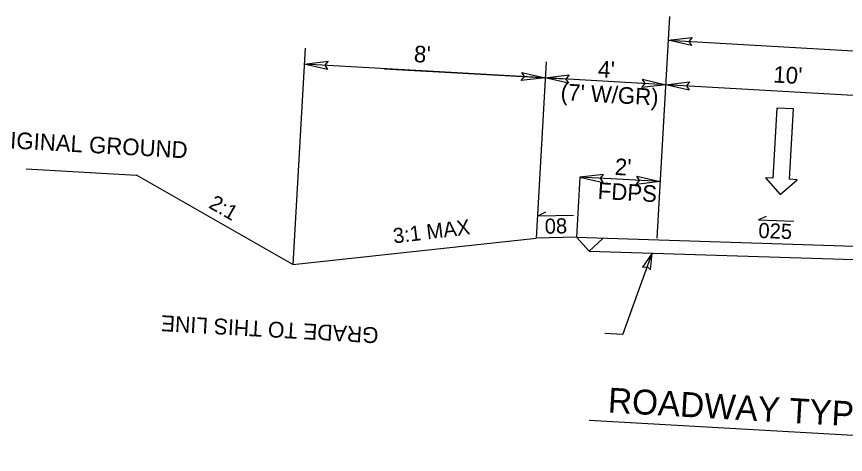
# Model space of a CAD drawing. Extents: x 2604316 to 2606605, y 617090 to 619543.
# Drawn here: x 2605915 to 2606244.6, y 617090 to 617264.2 of the extents above; entities that cross this region are included whole.
import ezdxf

# ---------------------------------------------------------------- set-up
doc = ezdxf.new("R2010")
doc.units = 0
for name, color, linetype in [('Pattern 1', 7, 'Continuous'), ('Prop Vertical Profile Curve Label', 7, 'Continuous'), ('Typical Pavement Slope CELL', 7, 'Continuous'), ('Typical Pavement Slope Information CELL', 7, 'Continuous'), ('Typical Terminator CELL', 7, 'Continuous'), ('Typical Text General CELL', 7, 'Continuous')]:
    doc.layers.add(name, color=color, linetype=linetype)

msp = doc.modelspace()

# ---------------------------------------------------------------- linework, layer by layer
at = {"layer": 'Pattern 1'}
msp.add_line((2605918.79, 617203.64), (2605962.72, 617201.14), dxfattribs=at)
at = {"layer": 'Prop Vertical Profile Curve Label'}
for p, q in [((2606024.79, 617165.55), (2605962.72, 617201.14)), ((2606024.79, 617165.55), (2606121.55, 617176.07)), ((2606137.6, 617176.44), (2606121.55, 617176.07)), ((2606137.6, 617176.44), (2606257.57, 617172.61)), ((2606137.6, 617176.44), (2606142.72, 617170.92)), ((2606148.28, 617176.1), (2606142.72, 617170.92)), ((2606142.72, 617170.92), (2606257.27, 617167.27)), ((2606156.03, 617137.78), (2606167.77, 617170.13)), ((2606156.03, 617137.78), (2606148.92, 617138.18))]:
    msp.add_line(p, q, dxfattribs=at)
at = {"layer": 'Typical Pavement Slope CELL'}
for p, q in [((2606174.65, 617264.19), (2606169.62, 617176.02)), ((2606174.11, 617254.77), (2606349.82, 617244.76)), ((2606029.7, 617251.68), (2606024.79, 617165.55)), ((2606125.18, 617239.83), (2606029.34, 617245.29)), ((2606125.54, 617246.22), (2606121.55, 617176.07)), ((2606061.28, 617243.47), (2606133.17, 617239.37)), ((2606173.1, 617237.1), (2606125.18, 617239.83)), ((2606260.96, 617232.1), (2606173.1, 617237.1)), ((2606217.35, 617227.82), (2606215.75, 617199.86)), ((2606223.94, 617227.44), (2606217.35, 617227.82)), ((2606222.34, 617199.49), (2606223.94, 617227.44)), ((2606138.96, 617200.36), (2606137.6, 617176.44)), ((2606170.91, 617198.54), (2606138.96, 617200.36)), ((2606215.75, 617199.86), (2606212.76, 617200.03)), ((2606212.76, 617200.03), (2606218.59, 617193.39)), ((2606218.59, 617193.39), (2606225.34, 617199.32)), ((2606225.34, 617199.32), (2606222.34, 617199.49)), ((2606125.29, 617186.35), (2606122.43, 617184.94)), ((2606122.43, 617184.94), (2606136.42, 617185.26)), ((2606212.99, 617184.61), (2606210.05, 617183.37)), ((2606210.05, 617183.37), (2606224.04, 617182.85)), ((2606142.71, 617103.71), (2606382.64, 617090.04))]:
    msp.add_line(p, q, dxfattribs=at)
at = {"layer": 'Typical Terminator CELL'}
for points in [[(2606183.38, 617252.63), (2606174.11, 617254.77), (2606183.61, 617255.9), (2606182.32, 617254.3)], [(2606038.6, 617243.14), (2606029.34, 617245.29), (2606038.84, 617246.42), (2606037.55, 617244.82)], [(2606115.91, 617241.97), (2606125.18, 617239.83), (2606115.67, 617238.7), (2606116.97, 617240.3)], [(2606134.45, 617237.69), (2606125.18, 617239.83), (2606134.68, 617240.96), (2606133.39, 617239.36)], [(2606163.84, 617239.25), (2606173.1, 617237.1), (2606163.6, 617235.97), (2606164.89, 617237.57)], [(2606182.37, 617234.96), (2606173.1, 617237.1), (2606182.61, 617238.23), (2606181.32, 617236.63)], [(2606148.41, 617201.44), (2606138.96, 617200.36), (2606148.27, 617198.16), (2606147.17, 617199.89)], [(2606161.64, 617200.68), (2606170.91, 617198.54), (2606161.4, 617197.41), (2606162.69, 617199.01)], [(2606167.05, 617163.41), (2606167.77, 617170.13), (2606163.94, 617164.5), (2606165.8, 617164.71)]]:
    msp.add_lwpolyline(points, close=True, dxfattribs=at)

# ---------------------------------------------------------------- texts
at = {"layer": 'Typical Pavement Slope CELL'}
for s, height, p in [("8'", 6.6, (2606072.85, 617246.12)), ("4'", 6.6, (2606146.05, 617240.07)), ("10'", 6.6, (2606215.74, 617237.98)), ("(7' W/GR)", 6.6, (2606131.2, 617231)), ("2'", 6.6, (2606152.7, 617201.23)), ('FDPS', 6.6, (2606145.94, 617191.7)), ('ROADWAY TYPICAL SECTION NO. 2', 9.9, (2606149.96, 617106.74))]:
    msp.add_text(s, height=height, rotation=356.7403, dxfattribs=at).set_placement(p)
at = {"layer": 'Typical Pavement Slope Information CELL'}
for s, rotation, p in [('2:1', 330.1752, (2605991.04, 617188.36)), ('3:1 MAX', 6.9509, (2606065.06, 617173.93)), ('08', 1.3142, (2606125.07, 617177.79)), ('025', 357.886, (2606209.87, 617176.17))]:
    msp.add_text(s, height=6, rotation=rotation, dxfattribs=at).set_placement(p)
at = {"layer": 'Typical Text General CELL'}
for s, height, rotation, p in [('ORIGINAL GROUND', 6.6, 356.7403, (2605899.12, 617212.54)), ('GRADE TO THIS LINE', 6.302, 176.7403, (2606059.1, 617140.48))]:
    msp.add_text(s, height=height, rotation=rotation, dxfattribs=at).set_placement(p)

doc.saveas('drawing.dxf')
